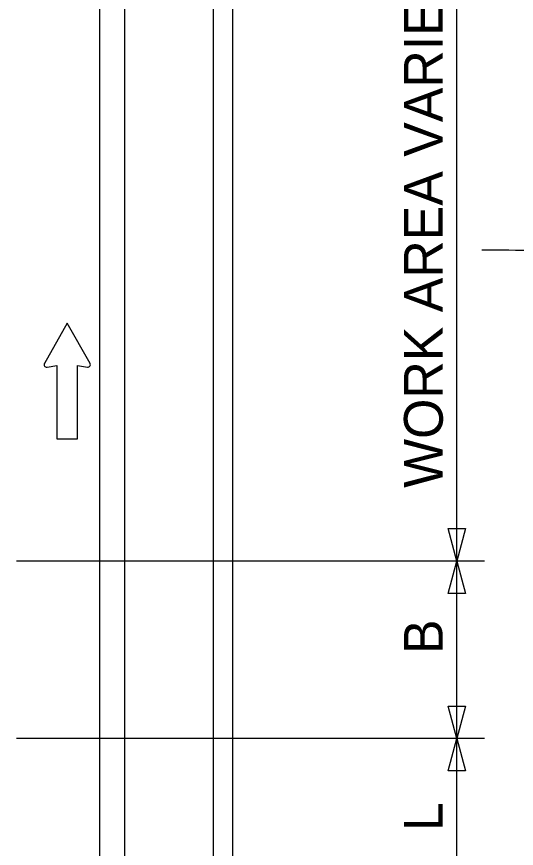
# Model space of a CAD drawing. Extents: x 16730 to 19504, y 5662 to 6979.
# Drawn here: x 17082.3 to 17172.5, y 6312.2 to 6462.5 of the extents above; entities that cross this region are included whole.
import ezdxf

# ---------------------------------------------------------------- set-up
doc = ezdxf.new("R2010")
doc.units = 0
for name, color, linetype in [('ALI_LEGAL_EX', 7, 'Continuous'), ('MT_SCRATCH_LEVEL_E', 7, 'Continuous'), ('PAVT_EDGE_EX', 7, 'Continuous'), ('TYPICAL_TEXT_DIMEN_PR', 7, 'Continuous')]:
    doc.layers.add(name, color=color, linetype=linetype)

msp = doc.modelspace()

# ---------------------------------------------------------------- linework, layer by layer
at = {"layer": 'ALI_LEGAL_EX'}
for p, q in [((17097.36, 6131.68), (17097.36, 6928.96)), ((17097.36, 6131.68), (17097.36, 6928.96)), ((17121.36, 6131.68), (17121.36, 6928.96)), ((17121.36, 6131.68), (17121.36, 6928.96))]:
    msp.add_line(p, q, dxfattribs=at)
at = {"layer": 'MT_SCRATCH_LEVEL_E'}
for p, q in [((17091.43, 6407.11), (17087.32, 6399.87)), ((17091.43, 6407.11), (17087.32, 6399.87)), ((17095.57, 6399.87), (17091.43, 6407.11)), ((17095.57, 6399.87), (17091.43, 6407.11)), ((17087.8, 6399.19), (17089.58, 6399.5)), ((17087.8, 6399.19), (17089.58, 6399.5)), ((17089.58, 6399.5), (17089.58, 6386.25)), ((17089.58, 6399.5), (17089.58, 6386.25)), ((17093.32, 6386.25), (17093.32, 6399.5)), ((17093.32, 6399.5), (17095.1, 6399.19)), ((17093.32, 6386.25), (17093.32, 6399.5)), ((17093.32, 6399.5), (17095.1, 6399.19)), ((17089.58, 6386.25), (17093.32, 6386.25)), ((17089.58, 6386.25), (17093.32, 6386.25))]:
    msp.add_line(p, q, dxfattribs=at)
for centre, start, end in [((17087.72, 6399.65), 150.4248, 279.9638), ((17087.72, 6399.65), 150.4248, 279.9638), ((17095.16, 6399.65), 260.0362, 29.7731), ((17095.16, 6399.65), 260.0362, 29.7731)]:
    msp.add_arc(centre, 0.463, start, end, dxfattribs=at)
at = {"layer": 'PAVT_EDGE_EX'}
for p, q in [((17101.81, 6869.88), (17101.81, 6101.02)), ((17117.81, 6869.88), (17117.81, 6101.02))]:
    msp.add_line(p, q, dxfattribs=at)
at = {"layer": 'TYPICAL_TEXT_DIMEN_PR'}
for p, q in [((17161.81, 6364.16), (17161.81, 6477.88)), ((17161.81, 6364.16), (17160.24, 6370.02)), ((17160.24, 6370.02), (17161.81, 6370.02)), ((17161.81, 6370.02), (17163.38, 6370.02)), ((17163.38, 6370.02), (17161.81, 6364.16)), ((17166.81, 6364.16), (17082.31, 6364.16)), ((17160.24, 6358.3), (17161.81, 6364.16)), ((17161.81, 6332.1), (17161.81, 6364.16)), ((17161.81, 6364.16), (17163.38, 6358.3)), ((17161.81, 6358.3), (17160.24, 6358.3)), ((17163.38, 6358.3), (17161.81, 6358.3)), ((17161.81, 6332.1), (17160.24, 6337.96)), ((17160.24, 6337.96), (17161.81, 6337.96)), ((17161.81, 6337.96), (17163.38, 6337.96)), ((17163.38, 6337.96), (17161.81, 6332.1)), ((17166.81, 6332.1), (17082.31, 6332.1)), ((17160.24, 6326.24), (17161.81, 6332.1)), ((17161.81, 6332.1), (17163.38, 6326.24)), ((17161.81, 6301.52), (17161.81, 6332.1)), ((17161.81, 6326.24), (17160.24, 6326.24)), ((17163.38, 6326.24), (17161.81, 6326.24))]:
    msp.add_line(p, q, dxfattribs=at)
msp.add_open_spline([(17166.32, 6420.38), (17218.61, 6420.38), (17218.61, 6409.77), (17183.28, 6409.77), (17183.28, 6396.96), (17237.46, 6396.96), (17237.46, 6396.96)], degree=2, dxfattribs=at)

# ---------------------------------------------------------------- texts
for s, p in [('WORK AREA VARIES', (17159.25, 6377.38)), ('B', (17159.25, 6347.36)), ('L', (17159.25, 6315.39))]:
    msp.add_text(s, height=7, rotation=90, dxfattribs=at).set_placement(p)

doc.saveas('drawing.dxf')
